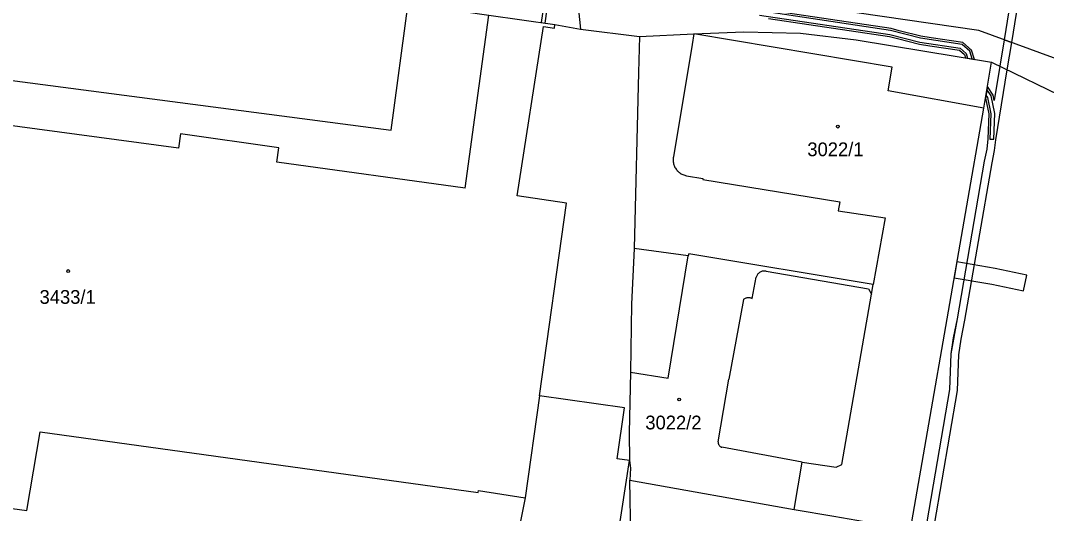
# Model space of a CAD drawing. Extents: x -869103 to -863415, y -1015889 to -1012477.
# Drawn here: x -866888.8 to -866761.8, y -1014122.2 to -1014061.3 of the extents above; entities that cross this region are included whole.
import ezdxf

# ---------------------------------------------------------------- set-up
doc = ezdxf.new("R2010")
doc.units = 0
for name, color, linetype in [('Hranice parcel', 7, 'Continuous'), ('Parcelní čísla', 7, 'Continuous'), ('Vnitřní kresba', 7, 'Continuous'), ('Věcná břemena k části', 7, 'Continuous'), ('Značky budov', 7, 'Continuous')]:
    doc.layers.add(name, color=color, linetype=linetype)

msp = doc.modelspace()

# ---------------------------------------------------------------- linework, layer by layer
at = {"layer": 'Hranice parcel'}
for p, q in [((-866819.45, -1014062.31), (-866812.14, -1014063.25)), ((-866812.14, -1014063.25), (-866812.27, -1014067.69)), ((-866812.14, -1014063.25), (-866805.44, -1014062.89)), ((-866769.55, -1014072.08), (-866768.57, -1014066.41)), ((-866768.57, -1014066.41), (-866755.46, -1014072.82)), ((-866812.27, -1014067.69), (-866812.8, -1014089.45)), ((-866778.62, -1014124.22), (-866769.55, -1014072.08)), ((-866806.14, -1014090.35), (-866812.8, -1014089.45)), ((-866806.06, -1014090.13), (-866806.14, -1014090.35)), ((-866813.41, -1014112.24), (-866813.37, -1014115.67)), ((-866817.48, -1014142.18), (-866813.37, -1014115.67)), ((-866813.33, -1014118.11), (-866793.02, -1014121.72)), ((-866813.1, -1014134.72), (-866813.33, -1014118.11))]:
    msp.add_line(p, q, dxfattribs=at)
for points in [[(-866930.13, -1014042.5), (-866899.94, -1014046.92), (-866874.89, -1014052.78), (-866819.92, -1014057.9), (-866819.45, -1014062.31)], [(-866722.31, -1014084.43), (-866731.08, -1014078.67), (-866736.16, -1014075.65), (-866739.84, -1014073.69), (-866741.21, -1014072.76), (-866748.09, -1014069.92), (-866751.69, -1014069.26), (-866770.16, -1014062.5), (-866803.21, -1014057.68), (-866822.18, -1014055.01)], [(-866842.89, -1014074.83), (-866840.77, -1014059.16), (-866830.78, -1014060.59), (-866822.61, -1014061.75), (-866819.45, -1014062.31)], [(-866933.46, -1014061.53), (-866920.6, -1014064.18), (-866920.65, -1014064.63), (-866842.89, -1014074.83)], [(-866805.44, -1014062.89), (-866799.23, -1014062.67), (-866792.23, -1014062.83), (-866785.32, -1014063.66), (-866768.57, -1014066.41)], [(-866812.8, -1014089.45), (-866813.14, -1014096.33), (-866813.28, -1014104.74), (-866813.41, -1014112.24)], [(-866787.8, -1014116.49), (-866787.11, -1014116.18), (-866783.45, -1014095.12), (-866783.23, -1014093.92), (-866806.06, -1014090.13)], [(-866813.37, -1014115.67), (-866814.9, -1014115.46), (-866814.02, -1014109.16), (-866824.54, -1014107.69), (-866826.32, -1014120.28), (-866827.79, -1014127.67), (-866830.73, -1014127.24), (-866830.78, -1014127.62), (-866830.41, -1014127.67), (-866831.66, -1014136.35), (-866832.04, -1014136.29), (-866832.09, -1014136.67), (-866831.72, -1014136.72), (-866832.2, -1014140.05), (-866825.14, -1014141.07), (-866825.27, -1014141.93), (-866822.17, -1014142.38), (-866822.05, -1014141.52), (-866817.48, -1014142.18)], [(-866813.37, -1014115.67), (-866813.28, -1014116.63), (-866813.33, -1014118.11)], [(-866793.02, -1014121.72), (-866792.02, -1014115.9), (-866787.8, -1014116.49)], [(-866793.02, -1014121.72), (-866788.1, -1014122.58), (-866778.62, -1014124.22)]]:
    msp.add_lwpolyline(points, dxfattribs=at)
at = {"layer": 'Vnitřní kresba'}
for p, q in [((-866833.73, -1014082.01), (-866830.78, -1014060.59)), ((-866827.28, -1014082.96), (-866824.04, -1014062)), ((-866824.04, -1014062), (-866822.68, -1014062.2)), ((-866822.68, -1014062.2), (-866822.61, -1014061.75)), ((-866805.44, -1014062.89), (-866805.65, -1014064.21)), ((-866780.88, -1014067.01), (-866805.44, -1014062.89)), ((-866805.65, -1014064.21), (-866807.95, -1014078.13)), ((-866781.38, -1014069.94), (-866780.88, -1014067.01)), ((-866769.55, -1014072.08), (-866781.38, -1014069.94)), ((-866869.22, -1014077.05), (-866893.35, -1014073.8)), ((-866868.97, -1014075.29), (-866869.22, -1014077.05)), ((-866856.8, -1014077.01), (-866868.97, -1014075.29)), ((-866857.04, -1014078.78), (-866856.8, -1014077.01)), ((-866833.73, -1014082.01), (-866857.04, -1014078.78)), ((-866806.32, -1014080.45), (-866804.3, -1014080.8)), ((-866804.3, -1014080.8), (-866804.33, -1014080.93)), ((-866804.33, -1014080.93), (-866787.36, -1014083.7)), ((-866821.19, -1014083.86), (-866827.28, -1014082.96)), ((-866824.54, -1014107.69), (-866821.19, -1014083.86)), ((-866787.36, -1014083.7), (-866787.56, -1014084.78)), ((-866787.56, -1014084.78), (-866781.73, -1014085.65)), ((-866781.73, -1014085.65), (-866783.23, -1014093.92)), ((-866808.6, -1014105.5), (-866806.14, -1014090.35)), ((-866796.46, -1014092.26), (-866783.83, -1014094.46)), ((-866798.21, -1014095.64), (-866797.71, -1014093)), ((-866783.83, -1014094.46), (-866783.45, -1014095.12)), ((-866799.3, -1014095.78), (-866801.11, -1014105.6)), ((-866813.28, -1014104.74), (-866808.6, -1014105.5)), ((-866802.41, -1014113.36), (-866801.11, -1014105.6)), ((-866887.99, -1014121.88), (-866886.32, -1014112.12)), ((-866886.32, -1014112.12), (-866832.12, -1014119.62)), ((-866792.02, -1014115.9), (-866801.98, -1014114.04)), ((-866832.12, -1014119.62), (-866832.09, -1014119.4)), ((-866832.09, -1014119.4), (-866826.32, -1014120.28)), ((-866894.35, -1014121.01), (-866887.99, -1014121.88))]:
    msp.add_line(p, q, dxfattribs=at)
for points in [[(-866807.95, -1014078.13), (-866807.97, -1014078.25), (-866807.98, -1014078.37), (-866807.99, -1014078.49), (-866807.98, -1014078.61), (-866807.97, -1014078.74), (-866807.95, -1014078.86), (-866807.93, -1014078.97), (-866807.9, -1014079.09), (-866807.85, -1014079.21), (-866807.81, -1014079.32), (-866807.76, -1014079.43), (-866807.69, -1014079.53), (-866807.63, -1014079.64), (-866807.55, -1014079.73), (-866807.47, -1014079.83), (-866807.39, -1014079.91), (-866807.3, -1014080), (-866807.21, -1014080.07), (-866807.11, -1014080.14), (-866807, -1014080.21), (-866806.9, -1014080.27), (-866806.79, -1014080.32), (-866806.67, -1014080.36), (-866806.56, -1014080.4), (-866806.44, -1014080.43), (-866806.32, -1014080.45)], [(-866796.46, -1014092.26), (-866796.55, -1014092.25), (-866796.64, -1014092.24), (-866796.72, -1014092.24), (-866796.81, -1014092.25), (-866796.9, -1014092.26), (-866796.98, -1014092.28), (-866797.07, -1014092.31), (-866797.15, -1014092.35), (-866797.23, -1014092.39), (-866797.3, -1014092.44), (-866797.37, -1014092.49), (-866797.44, -1014092.55), (-866797.5, -1014092.61), (-866797.55, -1014092.68), (-866797.6, -1014092.76), (-866797.64, -1014092.84), (-866797.68, -1014092.92), (-866797.71, -1014093)], [(-866799.3, -1014095.78), (-866799.24, -1014095.72), (-866799.18, -1014095.68), (-866799.11, -1014095.63), (-866799.05, -1014095.59), (-866798.97, -1014095.56), (-866798.9, -1014095.54), (-866798.82, -1014095.52), (-866798.74, -1014095.51), (-866798.66, -1014095.51), (-866798.58, -1014095.51), (-866798.5, -1014095.52), (-866798.43, -1014095.54), (-866798.35, -1014095.57), (-866798.28, -1014095.6), (-866798.21, -1014095.64)], [(-866802.41, -1014113.36), (-866802.41, -1014113.43), (-866802.41, -1014113.49), (-866802.4, -1014113.56), (-866802.39, -1014113.62), (-866802.36, -1014113.69), (-866802.33, -1014113.75), (-866802.3, -1014113.8), (-866802.26, -1014113.86), (-866802.21, -1014113.91), (-866802.16, -1014113.95), (-866802.1, -1014113.98), (-866802.04, -1014114.02), (-866801.98, -1014114.04)]]:
    msp.add_lwpolyline(points, dxfattribs=at)
at = {"layer": 'Věcná břemena k části'}
for points in [[(-866766.09, -1014063.99), (-866764.34, -1014053.19), (-866765.29, -1014052.86), (-866767.04, -1014063.64)], [(-866769.16, -1014069.8), (-866769.28, -1014070.51), (-866769.1, -1014070.78), (-866768.68, -1014072.79), (-866768.78, -1014075.92), (-866768.28, -1014075.94), (-866768.18, -1014072.75), (-866768.64, -1014070.58)], [(-866768.53, -1014093.87), (-866764.64, -1014094.69), (-866764.22, -1014092.74), (-866768.15, -1014091.91), (-866772.86, -1014091.1), (-866773.2, -1014093.07)]]:
    msp.add_lwpolyline(points, close=True, dxfattribs=at)
for points in [[(-866823.76, -1014057.54), (-866824.32, -1014061.51), (-866823.82, -1014061.58), (-866823.28, -1014057.71)], [(-866797.31, -1014060.58), (-866781.17, -1014063), (-866777.47, -1014063.93), (-866772.46, -1014064.69), (-866771.71, -1014065.33), (-866771.54, -1014065.92), (-866770.99, -1014066.01), (-866771.27, -1014065.05), (-866772.24, -1014064.21), (-866777.37, -1014063.44), (-866781.07, -1014062.51), (-866797.23, -1014060.08)], [(-866796.2, -1014061), (-866781.22, -1014063.24), (-866780.24, -1014063.5), (-866777.52, -1014064.17), (-866776.21, -1014064.39), (-866772.57, -1014064.92), (-866771.93, -1014065.47), (-866771.81, -1014065.88), (-866770.71, -1014066.06), (-866771.05, -1014064.91), (-866772.13, -1014063.98), (-866776.05, -1014063.41), (-866777.32, -1014063.19), (-866780, -1014062.54), (-866781.02, -1014062.26), (-866796.04, -1014060.02)], [(-866796.2, -1014061), (-866781.22, -1014063.24), (-866780.24, -1014063.5), (-866777.52, -1014064.17), (-866776.21, -1014064.39), (-866772.57, -1014064.92), (-866771.93, -1014065.47), (-866771.81, -1014065.88), (-866770.71, -1014066.06), (-866771.05, -1014064.91), (-866772.13, -1014063.98), (-866776.05, -1014063.41), (-866777.32, -1014063.19), (-866780, -1014062.54), (-866781.02, -1014062.26), (-866796.04, -1014060.02)], [(-866796.2, -1014061), (-866781.22, -1014063.24), (-866780.24, -1014063.5), (-866777.52, -1014064.17), (-866776.21, -1014064.39), (-866772.57, -1014064.92), (-866771.93, -1014065.47), (-866771.81, -1014065.88), (-866770.71, -1014066.06), (-866771.05, -1014064.91), (-866772.13, -1014063.98), (-866776.05, -1014063.41), (-866777.32, -1014063.19), (-866780, -1014062.54), (-866781.02, -1014062.26), (-866796.04, -1014060.02)], [(-866775.64, -1014123.61), (-866772.78, -1014107), (-866772.63, -1014102.6), (-866772.35, -1014100.69), (-866771.87, -1014098.32), (-866768.5, -1014078.85), (-866768.2, -1014077.33), (-866768.04, -1014076.01), (-866766.64, -1014067.36), (-866766.09, -1014063.99), (-866767.04, -1014063.64), (-866767.57, -1014066.9), (-866768.26, -1014071.15), (-866768.4, -1014070.48), (-866769.09, -1014069.44), (-866769.34, -1014070.88), (-866768.93, -1014072.81), (-866769.03, -1014075.9), (-866769.18, -1014077.17), (-866769.48, -1014078.67), (-866772.85, -1014098.14), (-866773.33, -1014100.51), (-866773.63, -1014102.5), (-866773.78, -1014106.9), (-866776.6, -1014123.27)], [(-866775.64, -1014123.61), (-866772.78, -1014107), (-866772.63, -1014102.6), (-866772.35, -1014100.69), (-866771.87, -1014098.32), (-866768.5, -1014078.85), (-866768.2, -1014077.33), (-866768.04, -1014076.01), (-866766.64, -1014067.36), (-866766.09, -1014063.99), (-866767.04, -1014063.64), (-866767.57, -1014066.9), (-866768.26, -1014071.15), (-866768.4, -1014070.48), (-866769.09, -1014069.44), (-866769.34, -1014070.88), (-866768.93, -1014072.81), (-866769.03, -1014075.9), (-866769.18, -1014077.17), (-866769.48, -1014078.67), (-866772.85, -1014098.14), (-866773.33, -1014100.51), (-866773.63, -1014102.5), (-866773.78, -1014106.9), (-866776.6, -1014123.27)], [(-866775.64, -1014123.61), (-866772.78, -1014107), (-866772.63, -1014102.6), (-866772.35, -1014100.69), (-866771.87, -1014098.32), (-866768.5, -1014078.85), (-866768.2, -1014077.33), (-866768.04, -1014076.01), (-866766.64, -1014067.36), (-866766.09, -1014063.99), (-866767.04, -1014063.64), (-866767.57, -1014066.9), (-866768.26, -1014071.15), (-866768.4, -1014070.48), (-866769.09, -1014069.44), (-866769.34, -1014070.88), (-866768.93, -1014072.81), (-866769.03, -1014075.9), (-866769.18, -1014077.17), (-866769.48, -1014078.67), (-866772.85, -1014098.14), (-866773.63, -1014102.5), (-866773.78, -1014106.9), (-866776.6, -1014123.27)]]:
    msp.add_lwpolyline(points, dxfattribs=at)
at = {"layer": 'Značky budov'}
for centre in [(-866787.6, -1014074.38), (-866882.85, -1014092.24), (-866807.25, -1014108.14)]:
    msp.add_circle(centre, 0.175, dxfattribs=at)

# ---------------------------------------------------------------- texts
at = {"layer": 'Parcelní čísla'}
for s, p in [('3022/1', (-866791.38, -1014078.04)), ('3433/1', (-866886.4, -1014096.3)), ('3022/2', (-866811.43, -1014111.83))]:
    msp.add_text(s, height=1.7, dxfattribs=at).set_placement(p)

doc.saveas('drawing.dxf')
